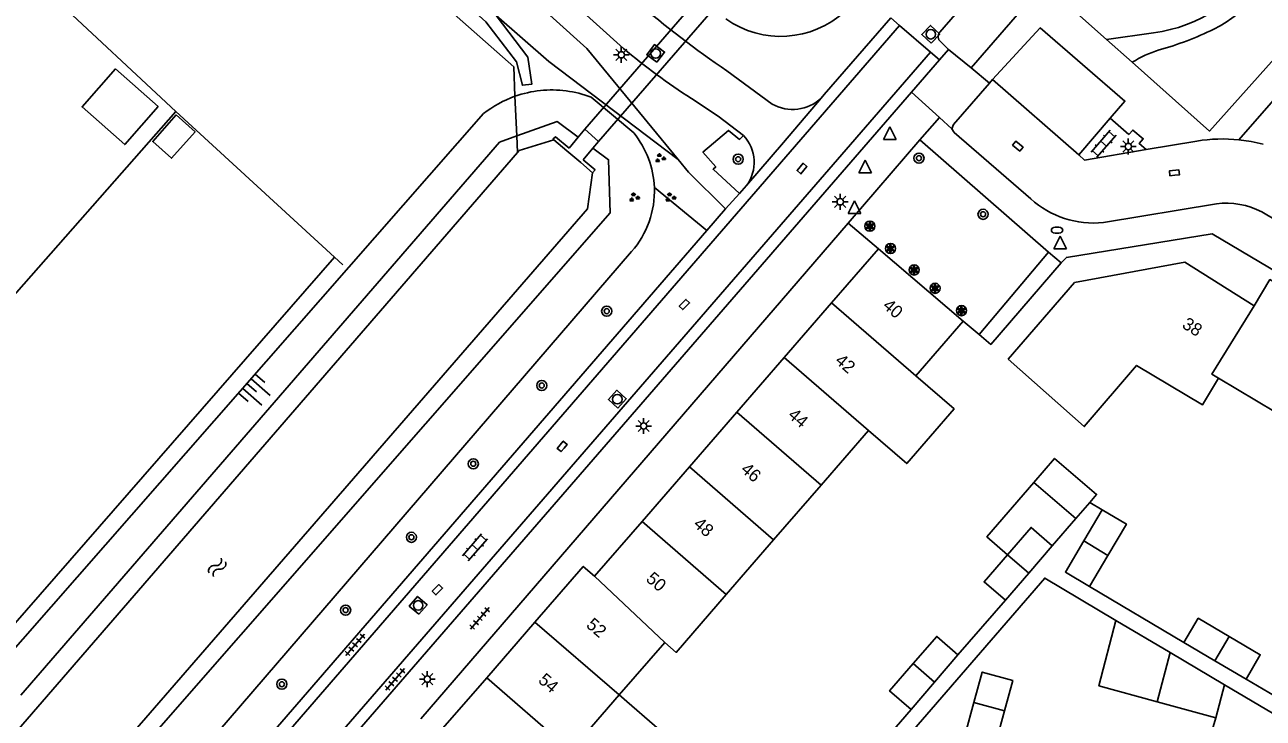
# Model space of a CAD drawing. Extents: x 128000 to 131008, y 398996 to 402500.
# Drawn here: x 128853.6 to 128951.5, y 399589.3 to 399644.1 of the extents above; entities that cross this region are included whole.
import ezdxf

# ---------------------------------------------------------------- set-up
doc = ezdxf.new("R2010")
doc.units = 0
for name, color, linetype in [('gg-afsc-erfafscheiding', 7, 'Continuous'), ('gg-afsc-hekwerk', 7, 'Continuous'), ('gg-anno-huisnummerreeks BGT', 7, 'Continuous'), ('gg-bbg-gedigitaliseerde bebouwing', 7, 'Continuous'), ('gg-bbg-gedigitaliseerde bijgebouw', 7, 'Continuous'), ('gg-bbg-hoofdgebouw', 7, 'Continuous'), ('gg-bbg-luifel en loopbrug', 7, 'Continuous'), ('gg-bbg-tussenscheiding', 7, 'Continuous'), ('gg-knt-BGT kruinlijn', 7, 'Continuous'), ('gg-knt-verharding', 7, 'Continuous'), ('gg-knt-verharding nz', 7, 'Continuous'), ('gg-kntw-beschoeiing', 7, 'Continuous'), ('gg-kntw-bovenkant insteek waterloop', 7, 'Continuous'), ('gg-kntw-greppel-droge sloot', 7, 'Continuous'), ('gg-kwrk-duiker nz vlak', 7, 'Continuous'), ('gg-kwrk-uitstroombak niveau min 01', 7, 'Continuous'), ('gt-grn-groengrens', 7, 'Continuous'), ('gt-grn-vlakafsluiter', 7, 'Continuous'), ('gt-grn-weggrens', 7, 'Continuous'), ('gt-symb-boom', 7, 'Continuous'), ('gt-symb-brandkraan', 7, 'Continuous'), ('gt-symb-groenvak', 7, 'Continuous'), ('gt-symb-klinker verharding', 7, 'Continuous'), ('gt-symb-kolk', 7, 'Continuous'), ('gt-symb-lichtmast', 7, 'Continuous'), ('gt-symb-rioolschacht', 7, 'Continuous'), ('gt-symb-solitaire heester', 7, 'Continuous'), ('gt-symb-talud symbool', 7, 'Continuous'), ('gt-symb-tegel verharding', 7, 'Continuous'), ('gt-symb-waterafsluiter', 7, 'Continuous'), ('gt-symb-watersymbool', 7, 'Continuous')]:
    doc.layers.add(name, color=color, linetype=linetype)

# ---------------------------------------------------------------- blocks, each defined once
blk = doc.blocks.new('gt0-LMAST')
at = {"layer": 'gt-symb-lichtmast'}
for p, q in [((-0.182, 0.173), (-0.447, 0.438)), ((-0.005, 0.246), (-0.005, 0.621)), ((0.172, 0.173), (0.437, 0.438)), ((-0.255, -0.004), (-0.63, -0.004)), ((-0.182, -0.181), (-0.447, -0.446)), ((-0.005, -0.254), (-0.005, -0.629)), ((0.437, -0.446), (0.172, -0.181)), ((0.245, -0.004), (0.62, -0.004))]:
    blk.add_line(p, q, dxfattribs=at)
blk.add_circle((-0.005, -0.004), 0.25, dxfattribs=at)
blk = doc.blocks.new('gt0-WAFSL')
at = {"layer": 'gt-symb-waterafsluiter'}
for p, q in [((-0.5, -0.333), (0, 0.667)), ((0, 0.667), (0.5, -0.333)), ((0.5, -0.333), (-0.5, -0.333))]:
    blk.add_line(p, q, dxfattribs=at)
blk = doc.blocks.new('gt0-SH')
at = {"layer": 'gt-symb-solitaire heester'}
blk.add_circle((0, 0), 0.4, dxfattribs=at)
for centre, start, end in [((-0.346, 0.2), 270, 30), ((-0.346, -0.2), 330, 90), ((0, 0.4), 210, 330), ((0.346, 0.2), 150, 270), ((0.346, -0.2), 90, 210), ((0, -0.4), 30, 150)]:
    blk.add_arc(centre, 0.4, start, end, dxfattribs=at)
blk = doc.blocks.new('gt0-BOOM')
at = {"layer": 'gt-symb-boom'}
for radius in [0.4, 0.2]:
    blk.add_circle((0, 0), radius, dxfattribs=at)
blk = doc.blocks.new('gt0-KOLK')
at = {"layer": 'gt-symb-kolk'}
blk.add_lwpolyline([(0, 0), (0.375, 0), (0.375, 0.4), (-0.375, 0.4), (-0.375, 0), (0, 0)], dxfattribs=at)
blk = doc.blocks.new('gt0-BR')
at = {"layer": 'gt-symb-brandkraan'}
for centre, radius, start, end in [((-0.244, 0), 0.206, 107.56694, 252.43307), ((0.599, -2.664), 3, 106.89205, 107.56694), ((0, -0.691), 0.938, 73.10799, 106.89205), ((-0.599, -2.664), 3, 72.43309, 73.10799), ((0.244, 0), 0.206, 287.56695, 72.43309), ((0.599, 2.664), 3, 252.43307, 253.10797), ((0, 0.691), 0.938, 253.10797, 286.89206), ((-0.599, 2.664), 3, 286.89206, 287.56695)]:
    blk.add_arc(centre, radius, start, end, dxfattribs=at)
blk = doc.blocks.new('gt0-RS')
at = {"layer": 'gt-symb-rioolschacht'}
blk.add_lwpolyline([(-0.5, -0.5), (0.5, -0.5), (0.5, 0.5), (-0.5, 0.5)], close=True, dxfattribs=at)
blk.add_circle((0, 0), 0.375, dxfattribs=at)
blk = doc.blocks.new('gt0-GRVAK')
at = {"layer": 'gt-symb-groenvak'}
for p, q in [((-0.11, 0.189), (-0.228, 0.24)), ((-0.182, 0.153), (0.088, 0.153)), ((-0.091, 0.211), (-0.156, 0.322)), ((-0.047, 0.214), (-0.047, 0.393)), ((-0.004, 0.211), (0.061, 0.322)), ((0.015, 0.189), (0.133, 0.24)), ((0.262, -0.052), (0.197, 0.059)), ((0.305, -0.049), (0.305, 0.13)), ((0.349, -0.052), (0.414, 0.059)), ((-0.245, -0.228), (-0.363, -0.177)), ((-0.318, -0.264), (-0.047, -0.264)), ((-0.226, -0.206), (-0.291, -0.095)), ((-0.183, -0.203), (-0.183, -0.024)), ((-0.139, -0.206), (-0.074, -0.095)), ((-0.12, -0.228), (-0.002, -0.177)), ((0.243, -0.074), (0.125, -0.023)), ((0.17, -0.11), (0.441, -0.11)), ((0.368, -0.074), (0.486, -0.023))]:
    blk.add_line(p, q, dxfattribs=at)
blk = doc.blocks.new('gt0-KL1')
at = {"layer": 'gt-symb-klinker verharding'}
for p, q in [((-1.15, 0.3), (1.15, 0.3)), ((-1, -0.3), (-1, 0.3)), ((-0.5, 0.3), (-0.5, 0.45)), ((0, -0.3), (0, 0.3)), ((0.5, 0.3), (0.5, 0.45)), ((1, -0.3), (1, 0.3)), ((-1.15, -0.3), (1.15, -0.3)), ((-0.5, -0.45), (-0.5, -0.3)), ((0.5, -0.45), (0.5, -0.3))]:
    blk.add_line(p, q, dxfattribs=at)
blk = doc.blocks.new('gt0-TEG1')
at = {"layer": 'gt-symb-tegel verharding'}
for p, q in [((-1.125, 0), (1.125, 0)), ((-0.9, -0.25), (-0.9, 0.25)), ((-0.45, -0.25), (-0.45, 0.25)), ((0, -0.25), (0, 0.25)), ((0.45, -0.25), (0.45, 0.25)), ((0.9, -0.25), (0.9, 0.25))]:
    blk.add_line(p, q, dxfattribs=at)
blk = doc.blocks.new('gt0-WA')
at = {"layer": 'gt-symb-watersymbool'}
for centre, start, end in [((-0.323, 0.022), 28.07249, 151.92751), ((0.427, 0.422), 208.07248, 331.92751), ((-0.323, -0.428), 28.07249, 151.92751), ((0.427, -0.028), 208.07248, 331.92751)]:
    blk.add_arc(centre, 0.425, start, end, dxfattribs=at)
blk = doc.blocks.new('gt0-TALUD_1')
at = {"layer": 'gt-symb-talud symbool'}
for p, q in [((-1, -1), (-1, 0)), ((-0.5, -2), (-0.5, 0)), ((0.5, -2), (0.5, 0)), ((1, -1), (1, 0)), ((0, -1), (0, 0))]:
    blk.add_line(p, q, dxfattribs=at)

msp = doc.modelspace()

# ---------------------------------------------------------------- linework, layer by layer
at = {"layer": 'gg-afsc-erfafscheiding'}
for p, q in [((128938.76, 399605.8), (128937.773, 399606.381)), ((128945.22, 399595.32), (128937.75, 399599.74)), ((128927.36, 399594.35), (128931.11, 399598.66)), ((128954.99, 399589.56), (128950.13, 399592.42)), ((128919.92, 399585.72), (128923.65, 399590.03))]:
    msp.add_line(p, q, dxfattribs=at)
msp.add_lwpolyline([(128939.85, 399597.07), (128934.224, 399600.408), (128910.157, 399572.595), (128909.922, 399571.746)], dxfattribs=at)
at = {"layer": 'gg-afsc-hekwerk'}
for p, q in [((128839.336, 399661.697), (128865.546, 399637.286)), ((128870.155, 399660.402), (128892.245, 399640.808)), ((128892.245, 399640.808), (128892.346, 399638.478)), ((128892.346, 399638.478), (128892.482, 399635.342)), ((128837.325, 399605.284), (128865.546, 399637.286)), ((128865.546, 399637.286), (128878.077, 399625.78)), ((128892.482, 399635.342), (128892.539, 399634.026)), ((128878.077, 399625.78), (128850.221, 399593.865)), ((128878.077, 399625.78), (128878.75, 399625.163))]:
    msp.add_line(p, q, dxfattribs=at)
at = {"layer": 'gg-bbg-gedigitaliseerde bebouwing'}
for p, q in [((128924.033, 399616.397), (128927.78, 399620.72)), ((128952.47, 399613.518), (128947.96, 399616.2)), ((128916.539, 399607.751), (128920.286, 399612.074)), ((128912.793, 399603.427), (128916.539, 399607.751)), ((128909.046, 399599.104), (128912.793, 399603.427)), ((128900.571, 399591.172), (128904.18, 399595.33)), ((128896.756, 399586.777), (128900.571, 399591.172))]:
    msp.add_line(p, q, dxfattribs=at)
for points in [[(128947.96, 399616.2), (128946.69, 399614.1), (128941.48, 399617.21), (128937.34, 399612.38), (128931.33, 399617.7)], [(128920.286, 399612.074), (128923.307, 399609.452), (128927.057, 399613.773), (128924.033, 399616.397)], [(128904.18, 399595.33), (128905.09, 399594.54), (128909.046, 399599.104)]]:
    msp.add_lwpolyline(points, dxfattribs=at)
at = {"layer": 'gg-bbg-gedigitaliseerde bijgebouw'}
for p, q in [((128936.69, 399605.12), (128933.37, 399607.97)), ((128937.773, 399606.381), (128936.69, 399605.12)), ((128938.76, 399605.8), (128937.305, 399603.34)), ((128932.965, 399600.81), (128934.82, 399602.96)), ((128937.75, 399599.74), (128939.215, 399602.205)), ((128931.11, 399598.66), (128932.965, 399600.81)), ((128939.85, 399597.07), (128944.141, 399594.524)), ((128947.675, 399593.87), (128945.22, 399595.32)), ((128925.505, 399592.19), (128927.36, 399594.35)), ((128944.141, 399594.524), (128948.43, 399591.98)), ((128950.13, 399592.42), (128947.675, 399593.87)), ((128923.65, 399590.03), (128925.505, 399592.19)), ((128948.43, 399591.98), (128952.809, 399589.382)), ((128931.038, 399589.914), (128928.626, 399590.571)), ((128943.106, 399590.641), (128947.74, 399589.372)), ((128947.74, 399589.372), (128947.378, 399588.121))]:
    msp.add_line(p, q, dxfattribs=at)
for points in [[(128864.149, 399637.668), (128861.503, 399634.668), (128858.128, 399637.644), (128860.774, 399640.644), (128864.149, 399637.668)], [(128933.37, 399607.97), (128934.998, 399609.867), (128938.318, 399607.017), (128937.773, 399606.381)], [(128939.215, 399602.205), (128940.68, 399604.67), (128938.76, 399605.8)], [(128934.82, 399602.96), (128933.14, 399604.41), (128931.28, 399602.255)], [(128937.305, 399603.34), (128935.85, 399600.88), (128937.75, 399599.74)], [(128931.28, 399602.255), (128929.42, 399600.1), (128931.11, 399598.66)], [(128939.85, 399597.07), (128938.498, 399591.903), (128943.106, 399590.641)], [(128945.22, 399595.32), (128946.35, 399597.24), (128948.805, 399595.795)], [(128927.36, 399594.35), (128925.69, 399595.8), (128923.82, 399593.65)], [(128948.805, 399595.795), (128951.26, 399594.35), (128950.13, 399592.42)], [(128923.82, 399593.65), (128921.95, 399591.5), (128923.65, 399590.03)], [(128928.626, 399590.571), (128929.283, 399592.983), (128931.695, 399592.326), (128931.038, 399589.914)]]:
    msp.add_lwpolyline(points, dxfattribs=at)
at = {"layer": 'gg-bbg-hoofdgebouw'}
for p, q in [((128921.07, 399626.43), (128917.375, 399622.167)), ((128927.78, 399620.72), (128921.07, 399626.43)), ((128917.375, 399622.167), (128913.628, 399617.844)), ((128913.628, 399617.844), (128909.881, 399613.521)), ((128909.881, 399613.521), (128906.135, 399609.197)), ((128906.135, 399609.197), (128902.388, 399604.874)), ((128902.388, 399604.874), (128898.64, 399600.55)), ((128893.927, 399596.934), (128890.113, 399592.539))]:
    msp.add_line(p, q, dxfattribs=at)
for points in [[(128950.78, 399621.93), (128945.28, 399625.37), (128936.58, 399623.76), (128931.33, 399617.7)], [(128956.959, 399621.068), (128952.02, 399624), (128950.78, 399621.93)], [(128898.64, 399600.55), (128897.74, 399601.33), (128893.927, 399596.934)], [(128890.113, 399592.539), (128886.28, 399588.12), (128890.067, 399584.856)]]:
    msp.add_lwpolyline(points, dxfattribs=at)
at = {"layer": 'gg-bbg-luifel en loopbrug'}
msp.add_line((128934.82, 399602.96), (128936.69, 399605.12), dxfattribs=at)
for points in [[(128865.564, 399637.004), (128867.064, 399635.681), (128865.212, 399633.581), (128863.712, 399634.904), (128865.564, 399637.004)], [(128933.37, 399607.97), (128929.643, 399603.675), (128931.28, 399602.255)], [(128900.571, 399591.172), (128903.97, 399588.223), (128900.155, 399583.827), (128896.756, 399586.777)], [(128928.626, 399590.571), (128927.968, 399588.159), (128930.38, 399587.502), (128931.038, 399589.914)]]:
    msp.add_lwpolyline(points, dxfattribs=at)
at = {"layer": 'gg-bbg-tussenscheiding'}
for p, q in [((128917.375, 399622.167), (128924.033, 399616.397)), ((128913.628, 399617.844), (128920.286, 399612.074)), ((128909.881, 399613.521), (128916.539, 399607.751)), ((128906.135, 399609.197), (128912.793, 399603.427)), ((128902.388, 399604.874), (128909.046, 399599.104)), ((128937.305, 399603.34), (128939.215, 399602.205)), ((128931.28, 399602.255), (128932.965, 399600.81)), ((128898.64, 399600.55), (128904.18, 399595.33)), ((128893.927, 399596.934), (128900.571, 399591.172)), ((128948.805, 399595.795), (128947.675, 399593.87)), ((128944.141, 399594.524), (128943.106, 399590.641)), ((128923.82, 399593.65), (128925.505, 399592.19)), ((128890.113, 399592.539), (128896.756, 399586.777)), ((128947.74, 399589.372), (128948.43, 399591.98))]:
    msp.add_line(p, q, dxfattribs=at)
msp.add_lwpolyline([(128950.78, 399621.93), (128947.432, 399616.514), (128947.96, 399616.2)], dxfattribs=at)
at = {"layer": 'gg-knt-BGT kruinlijn'}
for p, q in [((128901.731, 399635.579), (128898.37, 399638.41)), ((128889.871, 399637.112), (128851.185, 399593.01)), ((128844.627, 399560.119), (128901.57, 399626.21))]:
    msp.add_line(p, q, dxfattribs=at)
for centre, radius, start, end in [((128895.273, 399630.234), 8.748, 96.00773, 109.54415), ((128895.264, 399630.249), 8.732, 69.16103, 95.96029), ((128895.28, 399630.236), 8.748, 109.59702, 128.19328), ((128896.123, 399630.988), 7.248, 2.20429, 39.30336), ((128896.123, 399630.99), 7.247, 318.72813, 2.18688)]:
    msp.add_arc(centre, radius, start, end, dxfattribs=at)
at = {"layer": 'gg-knt-verharding'}
for p, q in [((128900.929, 399642.262), (128856.957, 399681.862)), ((128948.57, 399669.7), (128925.92, 399643.55)), ((128928.4, 399640.74), (128945.933, 399660.952)), ((128839.07, 399547.45), (128922.74, 399644.08)), ((128916.79, 399638.61), (128922.049, 399644.676)), ((128922.74, 399644.08), (128925.18, 399641.97)), ((128925.999, 399642.781), (128926.61, 399642.18)), ((128925.18, 399641.97), (128841.45, 399545.37)), ((128926.61, 399642.18), (128925.892, 399641.352)), ((128925.892, 399641.352), (128923.689, 399638.81)), ((128909.102, 399640.489), (128912.673, 399637.863)), ((128928.4, 399640.74), (128929.843, 399639.506)), ((128929.843, 399639.506), (128930.1, 399639.8)), ((128923.689, 399638.81), (128879.177, 399587.461)), ((128916.559, 399638.343), (128916.79, 399638.61)), ((128936.91, 399633.843), (128939.392, 399636.742)), ((128939.392, 399636.742), (128940.876, 399635.451)), ((128924.36, 399635.03), (128918.692, 399628.453)), ((128934.527, 399626.175), (128924.36, 399635.03)), ((128942.241, 399634.264), (128946.242, 399634.941)), ((128910.087, 399630.795), (128910.641, 399631.421)), ((128910.087, 399630.795), (128908.987, 399629.583)), ((128907.507, 399627.873), (128908.987, 399629.583)), ((128938.858, 399628.5), (128947.79, 399629.98)), ((128951.369, 399629.341), (129014.39, 399591.989)), ((128918.692, 399628.453), (128884.919, 399589.3)), ((128840.509, 399550.445), (128907.507, 399627.873)), ((128929.029, 399619.657), (128934.527, 399626.175))]:
    msp.add_line(p, q, dxfattribs=at)
for points in [[(128856.78, 399679.434), (128898.03, 399642.265), (128905.251, 399633.473)], [(128958.106, 399644.961), (128957.399, 399644.017), (128949.573, 399635.037)], [(128939.392, 399636.742), (128940.56, 399638.107), (128933.857, 399643.879), (128930.1, 399639.8)], [(128929.843, 399639.506), (128927, 399636.25), (128926.87, 399635.92)], [(128910.403, 399635.375), (128908.404, 399636.917), (128906.288, 399638.308)], [(128926.87, 399635.92), (128927.05, 399635.62), (128933.11, 399630.38)], [(128910.403, 399635.375), (128910.09, 399635.065), (128909.23, 399635.779), (128907.203, 399634.059), (128908.212, 399632.905), (128908.009, 399632.708), (128910.087, 399630.795)], [(128940.876, 399635.451), (128941.179, 399635.808), (128942.004, 399635.125), (128941.686, 399634.747), (128942.241, 399634.264)], [(128949.573, 399635.037), (128950.539, 399634.898), (128951.492, 399634.686)], [(128936.91, 399633.843), (128937.37, 399633.44), (128942.241, 399634.264)], [(128905.251, 399633.473), (128906.061, 399632.487), (128908.987, 399629.583)], [(128935.51, 399625.32), (128935.93, 399625.75), (128947.44, 399627.62), (129011.61, 399589.57)], [(128935.51, 399625.32), (128929.946, 399618.877), (128929.029, 399619.657)]]:
    msp.add_lwpolyline(points, dxfattribs=at)
for centre, radius, start, end in [((128950.271, 399701.54), 73.635, 229.0002, 236.00702), ((128926.308, 399643.201), 0.522, 138.0377, 233.69323), ((128933.969, 399681.434), 51.246, 229.85355, 237.30485), ((128914.292, 399640.727), 3.29, 240.52699, 313.55606), ((128908.21, 399633.259), 3.048, 322.91146, 43.97775), ((128948.269, 399622.437), 12.668, 84.0928, 99.20883), ((128938.095, 399635.893), 7.433, 227.88252, 275.89471), ((128948.586, 399624.094), 5.939, 62.05547, 97.69851)]:
    msp.add_arc(centre, radius, start, end, dxfattribs=at)
at = {"layer": 'gg-knt-verharding nz'}
msp.add_line((128930.1, 399639.8), (128936.91, 399633.843), dxfattribs=at)
at = {"layer": 'gg-kntw-beschoeiing'}
for points in [[(128895.417, 399635.029), (128892.69, 399634.2), (128892.539, 399634.026)], [(128892.539, 399634.026), (128835.82, 399568.52), (128835.84, 399566.22), (128835.995, 399566.092)], [(128898.479, 399632.434), (128898.07, 399629.591), (128840.68, 399563.47), (128839.23, 399563.28), (128839.102, 399563.4)]]:
    msp.add_lwpolyline(points, dxfattribs=at)
at = {"layer": 'gg-kntw-bovenkant insteek waterloop'}
for points in [[(128892.482, 399635.342), (128895.673, 399636.487), (128897.345, 399635.246)], [(128853.282, 399591.151), (128891.136, 399634.859), (128892.482, 399635.342)], [(128898.509, 399634.381), (128899.745, 399633.463), (128899.861, 399629.275), (128841.273, 399562.367), (128838.67, 399562.267), (128837.373, 399563.42)]]:
    msp.add_lwpolyline(points, dxfattribs=at)
msp.add_arc((128913.347, 399650.74), 7.525, 234.8051, 312.57455, dxfattribs=at)
at = {"layer": 'gg-kntw-greppel-droge sloot'}
msp.add_lwpolyline([(128854.27, 399676.241), (128872.931, 399659.811), (128890.053, 399644.369), (128892.476, 399641.204), (128892.936, 399639.346), (128893.669, 399639.427), (128893.377, 399641.571), (128890.852, 399644.857)], dxfattribs=at)
at = {"layer": 'gg-kwrk-duiker nz vlak'}
for p, q in [((128908.35, 399647.98), (128897.87, 399635.87)), ((128898.95, 399634.9), (128909.43, 399646.98))]:
    msp.add_line(p, q, dxfattribs=at)
at = {"layer": 'gg-kwrk-uitstroombak niveau min 01'}
for p, q in [((128897.345, 399635.246), (128897.87, 399635.87)), ((128897.87, 399635.87), (128898.95, 399634.9)), ((128895.417, 399635.029), (128896.44, 399634.17)), ((128896.622, 399634.387), (128897.345, 399635.246)), ((128898.95, 399634.9), (128898.509, 399634.381)), ((128896.44, 399634.17), (128897.541, 399633.242)), ((128898.509, 399634.381), (128897.729, 399633.463)), ((128897.541, 399633.242), (128898.479, 399632.434))]:
    msp.add_line(p, q, dxfattribs=at)
for points in [[(128896.622, 399634.387), (128895.561, 399635.272), (128895.352, 399635.083), (128895.417, 399635.029)], [(128898.479, 399632.434), (128898.684, 399632.667), (128897.729, 399633.463)]]:
    msp.add_lwpolyline(points, dxfattribs=at)
at = {"layer": 'gt-grn-groengrens'}
for p, q in [((128935.324, 399646.325), (128939.114, 399642.957)), ((128942.827, 399643.484), (128939.114, 399642.957)), ((128939.114, 399642.957), (128941.128, 399641.167)), ((128907.507, 399627.873), (128903.365, 399631.267))]:
    msp.add_line(p, q, dxfattribs=at)
for points in [[(128941.128, 399641.167), (128947.24, 399635.735), (128957.492, 399647.218)], [(128890.852, 399644.857), (128895.032, 399641.216), (128905.251, 399633.473)]]:
    msp.add_lwpolyline(points, dxfattribs=at)
for centre, radius, start, end in [((128942.365, 399654.01), 11.489, 297.08644, 341.09887), ((128941.11, 399655.611), 12.248, 278.05888, 327.84162), ((128936.022, 399667.774), 26.639, 285.77073, 295.75226), ((128946.054, 399633.171), 9.391, 107.2957, 121.6367)]:
    msp.add_arc(centre, radius, start, end, dxfattribs=at)
at = {"layer": 'gt-grn-vlakafsluiter'}
for p, q in [((128918.692, 399628.453), (128921.07, 399626.43)), ((128927.78, 399620.72), (128929.029, 399619.657))]:
    msp.add_line(p, q, dxfattribs=at)
at = {"layer": 'gt-grn-weggrens'}
for p, q in [((128922.74, 399644.08), (128922.049, 399644.676)), ((128925.892, 399641.352), (128925.18, 399641.97)), ((128926.61, 399642.18), (128928.4, 399640.74)), ((128923.689, 399638.81), (128925.897, 399636.804)), ((128913.561, 399634.83), (128916.559, 399638.343)), ((128924.36, 399635.03), (128925.897, 399636.804)), ((128925.897, 399636.804), (128926.87, 399635.92)), ((128913.561, 399634.83), (128910.641, 399631.421)), ((128935.51, 399625.32), (128934.527, 399626.175))]:
    msp.add_line(p, q, dxfattribs=at)

# ---------------------------------------------------------------- block references
at = {"layer": 'gt-symb-boom'}
for p in [(128924.281, 399633.592), (128909.989, 399633.508), (128929.344, 399629.153), (128899.598, 399621.499), (128894.464, 399615.627), (128889.056, 399609.441), (128884.161, 399603.634), (128878.965, 399597.879), (128873.923, 399592.023)]:
    msp.add_blockref('gt0-BOOM', p, dxfattribs=at)
at = {"layer": 'gt-symb-brandkraan'}
msp.add_blockref('gt0-BR', (128935.191, 399627.898), dxfattribs=at)
at = {"layer": 'gt-symb-groenvak'}
for p in [(128903.808, 399633.584), (128901.756, 399630.495), (128904.618, 399630.495)]:
    msp.add_blockref('gt0-GRVAK', p, dxfattribs=at)
at = {"layer": 'gt-symb-klinker verharding'}
for p, rotation in [((128938.873, 399634.732), 48.85180488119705), ((128889.186, 399602.845), 49.01346679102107)]:
    msp.add_blockref('gt0-KL1', p, dxfattribs=dict(at, rotation=rotation))
at = {"layer": 'gt-symb-kolk'}
for p, rotation in [((128932.218, 399634.691), 139.98904227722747), ((128915.187, 399632.639), 50.0697455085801), ((128944.491, 399632.235), 4.820766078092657), ((128905.879, 399621.885), 45.081040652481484), ((128896.229, 399610.686), 49.82757657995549), ((128886.358, 399599.349), 44.95950828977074)]:
    msp.add_blockref('gt0-KOLK', p, dxfattribs=dict(at, rotation=rotation))
at = {"layer": 'gt-symb-lichtmast'}
for p in [(128900.755, 399641.759), (128940.83, 399634.512), (128918.058, 399630.144), (128902.523, 399612.43), (128885.42, 399592.429)]:
    msp.add_blockref('gt0-LMAST', p, dxfattribs=at)
at = {"layer": 'gt-symb-rioolschacht'}
for p, rotation in [((128925.211, 399643.379), 46.62038199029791), ((128903.467, 399641.864), 53.37059891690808), ((128900.439, 399614.545), 47.83811877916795), ((128884.696, 399598.252), 49.01346678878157)]:
    msp.add_blockref('gt0-RS', p, dxfattribs=dict(at, rotation=rotation))
at = {"layer": 'gt-symb-solitaire heester'}
for p in [(128920.399, 399628.214), (128922.023, 399626.449), (128923.894, 399624.754), (128925.553, 399623.307), (128927.636, 399621.541)]:
    msp.add_blockref('gt0-SH', p, dxfattribs=at)
at = {"layer": 'gt-symb-talud symbool', "xscale": 0.9998924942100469, "yscale": 0.9998924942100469, "rotation": 48.770950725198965}
msp.add_blockref('gt0-TALUD_1', (128871.165, 399615.775), dxfattribs=at)
at = {"layer": 'gt-symb-tegel verharding'}
for p, rotation in [((128889.563, 399597.224), 49.01346679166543), ((128879.707, 399595.138), 49.013466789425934), ((128882.868, 399592.408), 49.01346679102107)]:
    msp.add_blockref('gt0-TEG1', p, dxfattribs=dict(at, rotation=rotation))
at = {"layer": 'gt-symb-waterafsluiter'}
for p in [(128921.969, 399635.394), (128920.028, 399632.777), (128919.176, 399629.556), (128935.435, 399626.756)]:
    msp.add_blockref('gt0-WAFSL', p, dxfattribs=at)
at = {"layer": 'gt-symb-watersymbool', "rotation": 50.4364913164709}
msp.add_blockref('gt0-WA', (128868.78, 399601.219), dxfattribs=at)

# ---------------------------------------------------------------- texts
at = {"layer": 'gg-anno-huisnummerreeks BGT'}
for s, rotation, p in [('40', 319.1, (128921.342, 399621.823)), ('38', 328, (128945, 399620.237)), ('42', 319.1, (128917.576, 399617.478)), ('44', 319.1, (128913.851, 399613.179)), ('46', 319.1, (128910.129, 399608.884)), ('48', 319.1, (128906.381, 399604.56)), ('50', 319.1, (128902.634, 399600.237)), ('52', 319.1, (128897.907, 399596.603)), ('54', 319.1, (128894.114, 399592.232))]:
    msp.add_text(s, height=1, rotation=rotation, dxfattribs=at).set_placement(p)

doc.saveas('drawing.dxf')
